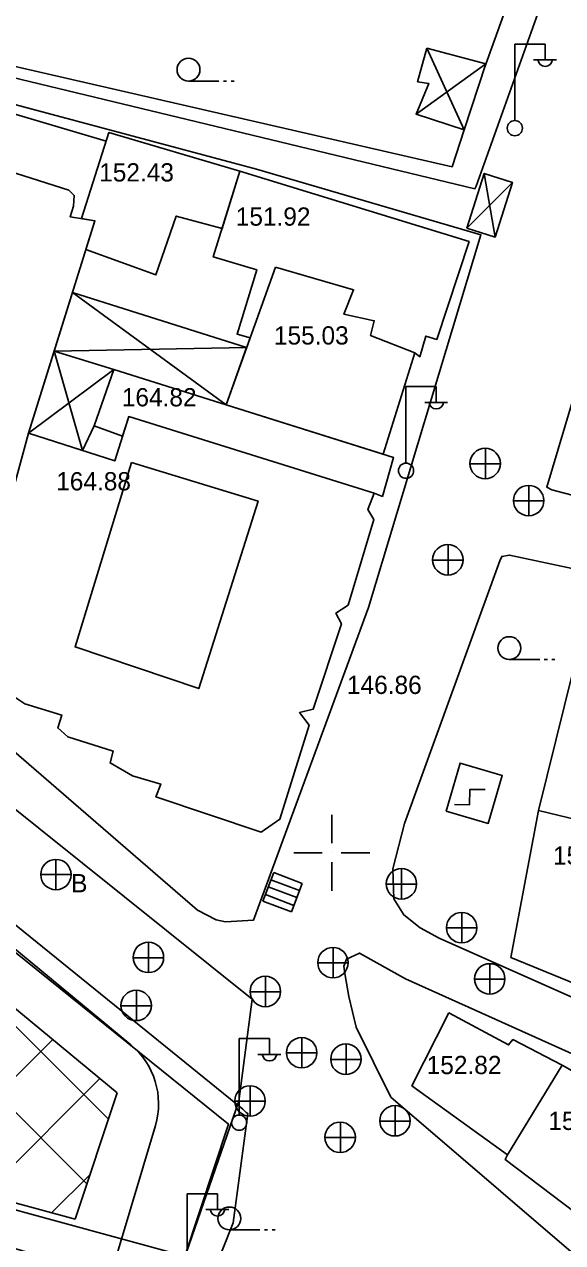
# Model space of a CAD drawing. Extents: x 419677 to 421689, y 4450851 to 4452923.
# Drawn here: x 420515.3 to 420550.7, y 4451960.1 to 4452040.1 of the extents above; entities that cross this region are included whole.
import ezdxf

# ---------------------------------------------------------------- set-up
doc = ezdxf.new("R2010")
doc.units = 0
for name, color, linetype in [('AA_HH', 7, 'Continuous'), ('Level 27', 7, 'Continuous'), ('Level 34', 7, 'Continuous'), ('Level 62', 7, 'Continuous'), ('Level 9', 7, 'Continuous')]:
    doc.layers.add(name, color=color, linetype=linetype)

msp = doc.modelspace()

# ---------------------------------------------------------------- linework, layer by layer
at = {"layer": 'AA_HH'}
for p, q in [((420541.771, 4452038.58), (420544.224, 4452033.213)), ((420547.546, 4452033.852), (420547.546, 4452038.852)), ((420547.546, 4452038.852), (420549.546, 4452038.852)), ((420549.546, 4452037.852), (420549.546, 4452038.852)), ((420545.655, 4452037.565), (420541.069, 4452034.242)), ((420548.786, 4452037.812), (420550.286, 4452037.812)), ((420526.124, 4452036.421), (420528.124, 4452036.421)), ((420528.424, 4452036.421), (420528.624, 4452036.421)), ((420528.924, 4452036.421), (420529.124, 4452036.421)), ((420518.511, 4452022.544), (420528.589, 4452015.158)), ((420529.944, 4452018.926), (420517.301, 4452018.671)), ((420517.301, 4452018.671), (420519.165, 4452012.155)), ((420521.217, 4452017.477), (420515.622, 4452013.296)), ((420540.4, 4452011.354), (420540.4, 4452016.354)), ((420540.4, 4452016.354), (420542.4, 4452016.354)), ((420542.4, 4452015.354), (420542.4, 4452016.354)), ((420541.64, 4452015.314), (420543.14, 4452015.314)), ((420545.622, 4452010.293), (420545.622, 4452012.293)), ((420544.602, 4452011.283), (420546.602, 4452011.283)), ((420548.48, 4452007.858), (420548.48, 4452009.858)), ((420547.46, 4452008.848), (420549.46, 4452008.848)), ((420543.173, 4452003.967), (420543.173, 4452005.967)), ((420542.153, 4452004.957), (420544.153, 4452004.957)), ((420547.192, 4451998.428), (420549.192, 4451998.428)), ((420549.492, 4451998.428), (420549.692, 4451998.428)), ((420549.992, 4451998.428), (420550.192, 4451998.428)), ((420535.536, 4451988.235), (420535.536, 4451986.36)), ((420533.036, 4451985.735), (420534.911, 4451985.735)), ((420535.536, 4451985.735), (420535.536, 4451985.735)), ((420536.161, 4451985.735), (420538.036, 4451985.735)), ((420517.418, 4451985.299), (420517.418, 4451983.299)), ((420535.536, 4451985.11), (420535.536, 4451983.235)), ((420540.122, 4451982.684), (420540.122, 4451984.684)), ((420516.418, 4451984.299), (420518.418, 4451984.299)), ((420531.721, 4451984.433), (420531.012, 4451982.563)), ((420531.721, 4451984.433), (420531.012, 4451982.563)), ((420531.542, 4451983.961), (420533.412, 4451983.253)), ((420533.591, 4451983.725), (420531.721, 4451984.433)), ((420533.591, 4451983.725), (420531.721, 4451984.433)), ((420531.367, 4451983.498), (420533.237, 4451982.79)), ((420532.883, 4451981.855), (420533.591, 4451983.725)), ((420532.883, 4451981.855), (420533.591, 4451983.725)), ((420539.102, 4451983.674), (420541.102, 4451983.674)), ((420531.012, 4451982.563), (420532.883, 4451981.855)), ((420531.012, 4451982.563), (420532.883, 4451981.855)), ((420531.173, 4451982.986), (420533.043, 4451982.277)), ((420544.08, 4451979.806), (420544.08, 4451981.806)), ((420543.06, 4451980.796), (420545.06, 4451980.796)), ((420523.508, 4451977.853), (420523.508, 4451979.853)), ((420535.626, 4451977.508), (420535.626, 4451979.508)), ((420522.488, 4451978.843), (420524.488, 4451978.843)), ((420534.606, 4451978.498), (420536.606, 4451978.498)), ((420545.923, 4451976.441), (420545.923, 4451978.441)), ((420531.186, 4451975.615), (420531.186, 4451977.615)), ((420522.703, 4451974.699), (420522.703, 4451976.699)), ((420544.903, 4451977.431), (420546.903, 4451977.431)), ((420530.166, 4451976.605), (420532.166, 4451976.605)), ((420521.683, 4451975.689), (420523.683, 4451975.689)), ((420529.443, 4451968.53), (420529.443, 4451973.53)), ((420529.443, 4451973.53), (420531.443, 4451973.53)), ((420531.443, 4451972.53), (420531.443, 4451973.53)), ((420533.573, 4451971.594), (420533.573, 4451973.594)), ((420536.478, 4451971.165), (420536.478, 4451973.165)), ((420530.683, 4451972.49), (420532.183, 4451972.49)), ((420532.553, 4451972.584), (420534.553, 4451972.584)), ((420535.458, 4451972.155), (420537.458, 4451972.155)), ((420530.18, 4451968.421), (420530.18, 4451970.421)), ((420529.16, 4451969.411), (420531.16, 4451969.411)), ((420539.703, 4451967.122), (420539.703, 4451969.122)), ((420536.097, 4451966.037), (420536.097, 4451968.037)), ((420538.683, 4451968.112), (420540.683, 4451968.112)), ((420535.077, 4451967.027), (420537.077, 4451967.027)), ((420526.027, 4451958.342), (420526.027, 4451963.342)), ((420526.027, 4451963.342), (420528.027, 4451963.342)), ((420528.027, 4451962.342), (420528.027, 4451963.342)), ((420527.267, 4451962.302), (420528.767, 4451962.302)), ((420528.809, 4451960.966), (420530.809, 4451960.966)), ((420531.109, 4451960.966), (420531.309, 4451960.966)), ((420531.609, 4451960.966), (420531.809, 4451960.966))]:
    msp.add_line(p, q, dxfattribs=at)
for points in [[(420549.367, 4452086.835), (420563.17, 4452083.995), (420563.344, 4452083.731), (420549.17, 4452041.157), (420545.009, 4452029.527), (420544.929, 4452029.347), (420508.387, 4452038.146)], [(420508.4, 4452036.565), (420530.587, 4452030.628), (420545.328, 4452026.317), (420537.954, 4452001.843), (420530.399, 4451981.31), (420528.554, 4451981.201), (420527.934, 4451981.337), (420526.707, 4451981.975), (420499.807, 4452005.231), (420464.659, 4452032.205), (420443.858, 4452051.317), (420443.678, 4452051.435), (420443.655, 4452051.803), (420443.66, 4452051.913), (420443.781, 4452052.202), (420443.784, 4452052.276), (420444.021, 4452052.707), (420444.369, 4452053.134), (420445.547, 4452054.115), (420447.422, 4452055.032), (420465.82, 4452055.652)], [(420543.445, 4452030.781), (420507.665, 4452038.999), (420490.602, 4452042.859)], [(420547.14, 4452041.666), (420545.542, 4452037.222)], [(420506.668, 4452036.632), (420520.716, 4452032.48)], [(420544.224, 4452033.213), (420543.445, 4452030.781)], [(420546.257, 4452026.172), (420545.545, 4452030.351)], [(420544.405, 4452026.759), (420547.397, 4452029.763)], [(420496.188, 4451996.012), (420529.687, 4451968.897), (420529.922, 4451968.674), (420530.011, 4451968.609), (420529.068, 4451961.438), (420528.328, 4451959.613), (420527.683, 4451958.666), (420526.855, 4451957.727), (420526.445, 4451957.348), (420525.942, 4451956.943), (420525.442, 4451956.599), (420497.103, 4451964.914), (420456.088, 4451977.828), (420455.727, 4451977.934), (420455.433, 4451978.22), (420466.391, 4452008.433), (420470.421, 4452015.873)], [(420511.845, 4451999.454), (420515.622, 4452013.296), (420521.285, 4452011.473), (420522.203, 4452014.383), (420538.317, 4452009.352), (420537.895, 4452008.288), (420538.293, 4452007.614), (420536.614, 4452002), (420535.809, 4452001.481), (420536.164, 4452000.767), (420534.315, 4451995.159), (420533.415, 4451994.942), (420534.042, 4451994.11), (420532.129, 4451987.932), (420530.886, 4451987.093), (420523.989, 4451989.412), (420524.297, 4451990.248), (420522.449, 4451990.79), (420520.974, 4451991.635), (420521.174, 4451992.412), (420518.194, 4451993.34), (420517.538, 4451993.94), (420517.803, 4451994.777), (420515.368, 4451995.513), (420514.581, 4451996.033)], [(420702.21, 4451935.845), (420687.724, 4451939.317), (420636.039, 4451952.377), (420606.855, 4451957.803), (420581.37, 4451963.147), (420580.063, 4451963.458), (420542.587, 4451980.129), (420541.331, 4451980.804), (420540.264, 4451981.653), (420539.607, 4451982.704), (420539.536, 4451984.683), (420540.309, 4451987.649), (420546.575, 4452004.907), (420546.696, 4452005.195), (420547.212, 4452005.283), (420561.716, 4452002.19), (420589.529, 4451995.432), (420620.295, 4451988.257), (420651.436, 4451981.323), (420673.705, 4451976.223), (420686.215, 4451973.689), (420702.224, 4451971.63), (420702.585, 4451971.6)], [(420545.597, 4451989.88), (420544.597, 4451989.89), (420544.588, 4451988.89), (420543.588, 4451988.9)]]:
    msp.add_lwpolyline(points, dxfattribs=at)
for points in [[(420670.878, 4452024.153), (420685.229, 4452021.295), (420685.812, 4452021.198), (420683.01, 4451995.858), (420680.354, 4451978.203), (420662.951, 4451981.882), (420659.607, 4451983.704), (420657.366, 4451984.601), (420654.603, 4451985.3), (420624.839, 4451991.097), (420585.696, 4452000.208), (420549.976, 4452009.581), (420549.652, 4452009.741), (420561.271, 4452048.748), (420561.435, 4452049.217), (420579.914, 4452044.871), (420613.247, 4452037.39), (420651.639, 4452028.787), (420665.358, 4452025.698)], [(420541.771, 4452038.58), (420545.655, 4452037.565), (420544.224, 4452033.213), (420541.069, 4452034.242), (420541.897, 4452036.263), (420541.172, 4452036.378)], [(420529.493, 4452030.497), (420520.893, 4452033.037), (420519.099, 4452027.385), (420519.98, 4452027.245), (420519.388, 4452025.349), (420523.981, 4452023.695), (420525.319, 4452027.549), (420528.325, 4452026.736)], [(420505.587, 4452031.213), (420508.887, 4452030.206), (420509.233, 4452031.488), (420509.629, 4452031.833), (420510.35, 4452031.782), (420518.27, 4452029.248), (420518.619, 4452028.915), (420518.571, 4452028.216), (420518.353, 4452027.503), (420519.98, 4452027.245), (420515.622, 4452013.296), (420512.584, 4452002.161), (420510.799, 4452002.743), (420510.633, 4452004.535), (420507.766, 4452005.183), (420507.324, 4452007.538), (420504.015, 4452008.311), (420503.837, 4452010.336), (420501.692, 4452010.955), (420501.886, 4452011.584), (420500.161, 4452012.08)], [(420529.493, 4452030.497), (420527.75, 4452024.885), (420530.605, 4452024.025), (420529.318, 4452019.794), (420530.167, 4452019.547), (420528.589, 4452015.158), (420538.909, 4452011.912), (420540.987, 4452018.581), (420541.316, 4452018.313), (420541.708, 4452019.675), (420542.442, 4452019.454), (420544.556, 4452025.878)], [(420544.405, 4452026.759), (420545.545, 4452030.351), (420547.397, 4452029.763), (420546.257, 4452026.172)], [(420531.837, 4452024.195), (420536.961, 4452022.712), (420536.327, 4452021.105), (420538.328, 4452020.684), (420538.079, 4452019.718), (420540.987, 4452018.581), (420538.909, 4452011.912), (420528.589, 4452015.158)], [(420529.944, 4452018.926), (420518.511, 4452022.544), (420517.301, 4452018.671), (420521.217, 4452017.477), (420528.589, 4452015.158)], [(420521.217, 4452017.477), (420517.301, 4452018.671), (420515.622, 4452013.296), (420519.165, 4452012.155), (420519.932, 4452013.783)], [(420521.217, 4452017.477), (420539.596, 4452011.696), (420538.861, 4452009.139), (420538.317, 4452009.352), (420522.203, 4452014.383), (420521.796, 4452013.092), (420519.932, 4452013.783)], [(420522.39, 4452011.369), (420530.698, 4452008.828), (420526.794, 4451996.516), (420518.675, 4451999.251)], [(420562.407, 4452000.361), (420560.075, 4451989.192), (420558.634, 4451989.632), (420557.904, 4451986.392), (420549.103, 4451988.501), (420552.523, 4452002.313)], [(420543.041, 4451988.467), (420545.808, 4451987.659), (420546.729, 4451990.817), (420543.962, 4451991.624)], [(420556.111, 4451975.246), (420547.3, 4451978.856), (420549.103, 4451988.501), (420557.904, 4451986.392), (420560.429, 4451985.549)], [(420510.223, 4451982.829), (420504.387, 4451965.097), (420525.887, 4451959.228), (420528.75, 4451967.914)], [(420599.898, 4451956.597), (420619.688, 4451952.078), (420620.67, 4451951.854), (420614.923, 4451930.111), (420610.459, 4451914.103), (420610.151, 4451913.712), (420609.283, 4451913.089), (420608.057, 4451912.7), (420606.696, 4451912.61), (420606.221, 4451912.666), (420575.227, 4451938.97), (420539.411, 4451969.686), (420537.128, 4451974.287), (420536.654, 4451976.285), (420536.382, 4451977.798), (420536.326, 4451978.277), (420536.491, 4451978.746), (420537.351, 4451979.15), (420540.368, 4451977.45), (420562.41, 4451967.526), (420578.439, 4451960.635), (420594.329, 4451957.779)], [(420543.218, 4451975.227), (420540.794, 4451970.427), (420547.074, 4451965.894), (420550.66, 4451971.787), (420547.431, 4451973.464), (420547.148, 4451973.118)], [(420550.66, 4451971.787), (420552.635, 4451970.676), (420552.848, 4451970.98), (420561.407, 4451966.555), (420556.924, 4451958.014), (420546.928, 4451965.587), (420547.074, 4451965.894)]]:
    msp.add_lwpolyline(points, close=True, dxfattribs=at)
for centre, radius in [((420526.124, 4452037.171), 0.75), ((420547.557, 4452033.328), 0.5), ((420545.607, 4452011.301), 1), ((420540.41, 4452010.83), 0.5), ((420548.465, 4452008.866), 1), ((420543.158, 4452004.975), 1), ((420547.192, 4451999.178), 0.75), ((420517.418, 4451984.299), 1), ((420540.107, 4451983.692), 1), ((420544.064, 4451980.814), 1), ((420523.492, 4451978.861), 1), ((420535.611, 4451978.516), 1), ((420545.908, 4451977.449), 1), ((420531.171, 4451976.623), 1), ((420522.688, 4451975.707), 1), ((420533.558, 4451972.602), 1), ((420536.463, 4451972.174), 1), ((420530.165, 4451969.429), 1), ((420539.687, 4451968.131), 1), ((420529.453, 4451968.006), 0.5), ((420536.082, 4451967.045), 1), ((420528.809, 4451961.716), 0.75)]:
    msp.add_circle(centre, radius, dxfattribs=at)
for centre in [(420549.547, 4452037.856), (420542.4, 4452015.358), (420531.443, 4451972.534), (420528.028, 4451962.346)]:
    msp.add_arc(centre, 0.474, 184.83843, 355.14641, dxfattribs=at)
at = {"layer": 'Level 27'}
msp.add_line((420521.437, 4451969.969), (420518.682, 4451961.66), dxfattribs=at)
msp.add_line((420521.437, 4451969.969), (420518.682, 4451961.66), dxfattribs=at)
for points in [[(420462.531, 4452018.712), (420521.437, 4451969.969)], [(420462.531, 4452018.712), (420521.437, 4451969.969)], [(420518.682, 4451961.66), (420504.41, 4451965.54), (420489.67, 4451969.67), (420475.44, 4451973.55), (420461.29, 4451977.71), (420448.817, 4451981.269)], [(420518.682, 4451961.66), (420504.41, 4451965.54), (420489.67, 4451969.67), (420475.44, 4451973.55), (420461.29, 4451977.71), (420448.817, 4451981.269)]]:
    msp.add_lwpolyline(points, dxfattribs=at)
at = {"layer": 'Level 34'}
for p, q in [((420519.454, 4451963.989), (420475.284, 4452008.159)), ((420519.454, 4451963.989), (420475.284, 4452008.159)), ((420520.863, 4451968.237), (420508.071, 4451981.029)), ((420520.863, 4451968.237), (420508.071, 4451981.029)), ((420508.24, 4451964.499), (420517.209, 4451973.467)), ((420508.24, 4451964.499), (420517.209, 4451973.467)), ((420512.688, 4451963.29), (420520.305, 4451970.906)), ((420512.688, 4451963.29), (420520.305, 4451970.906)), ((420517.136, 4451962.08), (420519.658, 4451964.602)), ((420517.136, 4451962.08), (420519.658, 4451964.602))]:
    msp.add_line(p, q, dxfattribs=at)
at = {"layer": 'Level 62'}
for points in [[(420462.834, 4452022.355), (420522.344, 4451973.112)], [(420462.834, 4452022.355), (420522.344, 4451973.112)], [(420523.947, 4451967.829), (420515.069, 4451938.106), (420511.696, 4451927.522)], [(420523.947, 4451967.829), (420515.069, 4451938.106), (420511.696, 4451927.522)]]:
    msp.add_lwpolyline(points, dxfattribs=at)
msp.add_arc((420519.156, 4451969.26), 5, 343.36957, 50.39313, dxfattribs=at)
msp.add_arc((420519.156, 4451969.26), 5, 343.36957, 50.39313, dxfattribs=at)
at = {"layer": 'Level 9'}
for p, q in [((420467.141, 4452026.757), (420530.303, 4451976.117)), ((420467.141, 4452026.757), (420530.303, 4451976.117)), ((420530.303, 4451976.117), (420529.432, 4451969.417)), ((420530.303, 4451976.117), (420529.432, 4451969.417)), ((420529.432, 4451969.417), (420506.766, 4451904.034)), ((420529.432, 4451969.417), (420506.766, 4451904.034))]:
    msp.add_line(p, q, dxfattribs=at)

# ---------------------------------------------------------------- texts
at = {"layer": 'AA_HH'}
for s, p in [('152.43 ', (420520.258, 4452029.826)), ('151.92 ', (420529.228, 4452026.923)), ('155.03', (420531.736, 4452019.117)), ('164.82 ', (420521.745, 4452015.055)), ('164.88 ', (420517.436, 4452009.535)), ('146.86 ', (420536.531, 4451996.164)), ('152.17', (420550.061, 4451984.953)), ('B', (420518.418, 4451983.138)), ('152.82', (420541.767, 4451971.195)), ('152.70 ', (420549.757, 4451967.528))]:
    msp.add_text(s, height=1.2, dxfattribs=at).set_placement(p)

doc.saveas('drawing.dxf')
